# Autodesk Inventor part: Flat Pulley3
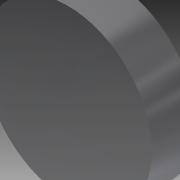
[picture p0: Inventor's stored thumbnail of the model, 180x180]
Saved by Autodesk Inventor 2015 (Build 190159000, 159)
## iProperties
Created: 2007-02
Part Number: Flat Pulley3
Material: Steel
Document SubType Name: Modeling
Designer: Autodesk, Inc.
Density: 7.85 g/cm^3
Mass: 3756.38 g
Surface Area: 418.946 cm^2
Volume: 478.52 cm^3
Appearance: Light Gray Reflective
CustomPartVersion: 1
Author: Autodesk, Inc.
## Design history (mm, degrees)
sketch "Main Sketch"
  geometry: C1 r 66.04 at (0, 0); 1 further point
  constraints: 1 centre point, 1 coincident
  dimensions: "d0" = 132.08 diameter of C1 (= da_D)
extrude "Pulley" new body sketch "Main Sketch" stored distance "d1" = 34.925 (= da_B); taper "d2" = 0 deg
body "Solid1"
other parameters: "da_D" = 132.08 [user parameter; used in 1 equation term], "da_B" = 34.925 [user parameter; used in 1 equation term], "d3" = 0, "d4" = 0
